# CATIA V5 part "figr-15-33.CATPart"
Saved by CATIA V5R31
Part number: Part1
Bounding box of the stored display mesh (mm): x -40.264 to 42.014, y -25.445 to 25.445, z -51 to 0.75
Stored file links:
  D:\PROJECTS\Project 2021\US EDITION\CATIA V5 6R 2021\Resources\Part Files\c15_catia_v5_6r2021_prt\figr-15-33.CATPart
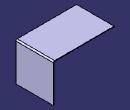
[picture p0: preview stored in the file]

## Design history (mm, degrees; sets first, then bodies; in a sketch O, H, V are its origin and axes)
SheetMetalParameters1: Thickness 0.75, BendRadius 1, KFactor 0.356492 {= log(min(100,max(20*SheetMetalParameters1.BendRadius,SheetMetalParameters1.Thickness)/SheetMetalParameters1.Thickness))/log(100)/2}, ReliefRadialLength 1, ReliefAxialLength 2, MinimumBendRadius 0
Body1 (main body)
  Sketch1 on xy-plane, origin (0, 0, 0), H (1, 0, 0), V (0, 1, 0)
    line L1 (-40.2643, 25.445) -> (40.2643, 25.445)
    line L2 (40.2643, 25.445) -> (40.2643, -25.445)
    line L3 (40.2643, -25.445) -> (-40.2643, -25.445)
    line L4 (-40.2643, -25.445) -> (-40.2643, 25.445)
    horizontal: L1 H, L3 H
    vertical: L2 V, L4 V
    symmetry: L1 L3 H, L4 L2 V
  Wall1: Thickness 0.75, Profile Sketch1
  Flange1: Angle 90, Length 50, Radius 1, KFacteur 0.356492 {= log(min(100,max(20*Flange1.Radius,SheetMetalParameters1.Thickness)/SheetMetalParameters1.Thickness))/log(100)/2}, Guide edge [face of Wall1 | face of Wall1]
